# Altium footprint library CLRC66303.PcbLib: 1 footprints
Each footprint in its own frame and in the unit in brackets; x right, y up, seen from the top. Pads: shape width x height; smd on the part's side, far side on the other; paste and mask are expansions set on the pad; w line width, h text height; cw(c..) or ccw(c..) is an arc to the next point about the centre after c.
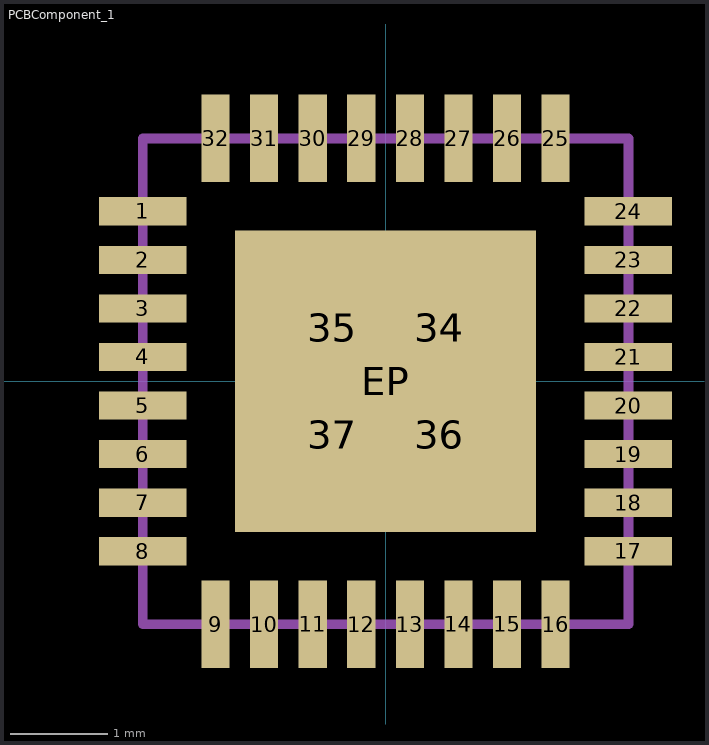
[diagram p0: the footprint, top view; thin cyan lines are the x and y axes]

## PCBComponent_1 [mm]
pads (38):
  rect 0.9x0.29 smd paste-0.025 mask+0.025: 1(-2.5,1.75) 2(-2.5,1.25) 3(-2.5,0.75) 4(-2.5,0.25) 5(-2.5,-0.25) 6(-2.5,-0.75) 7(-2.5,-1.25) 8(-2.5,-1.75) 17(2.5,-1.75) 18(2.5,-1.25) 19(2.5,-0.75) 20(2.5,-0.25) 21(2.5,0.25) 22(2.5,0.75) 23(2.5,1.25) 24(2.5,1.75)
  rect 0.29x0.9 smd paste-0.025 mask+0.025: 9(-1.75,-2.5) 10(-1.25,-2.5) 11(-0.75,-2.5) 12(-0.25,-2.5) 13(0.25,-2.5) 14(0.75,-2.5) 15(1.25,-2.5) 16(1.75,-2.5) 25(1.75,2.5) 26(1.25,2.5) 27(0.75,2.5) 28(0.25,2.5) 29(-0.25,2.5) 30(-0.75,2.5) 31(-1.25,2.5) 32(-1.75,2.5)
  rect 0.7x0.7 on Top Paste: 34(0.55,0.55) 35(-0.55,0.55) 36(0.55,-0.55) 37(-0.55,-0.55)
  round 0.7 on Mech8: 38(-3.25,2.75)
  rect 3.1x3.1 smd paste-3.1 mask+0.025: EP(0,0)
Assembly Top:
  lines w0.1: -2.5,-2.5 -2.5,2.5 2.5,2.5 2.5,-2.5 -2.5,-2.5
  text ".Designator" at -3.25,-3.5 h0.51
3D body: height 0.97, standoff -0.03, extent -2.5,-2.5 2.5,2.5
